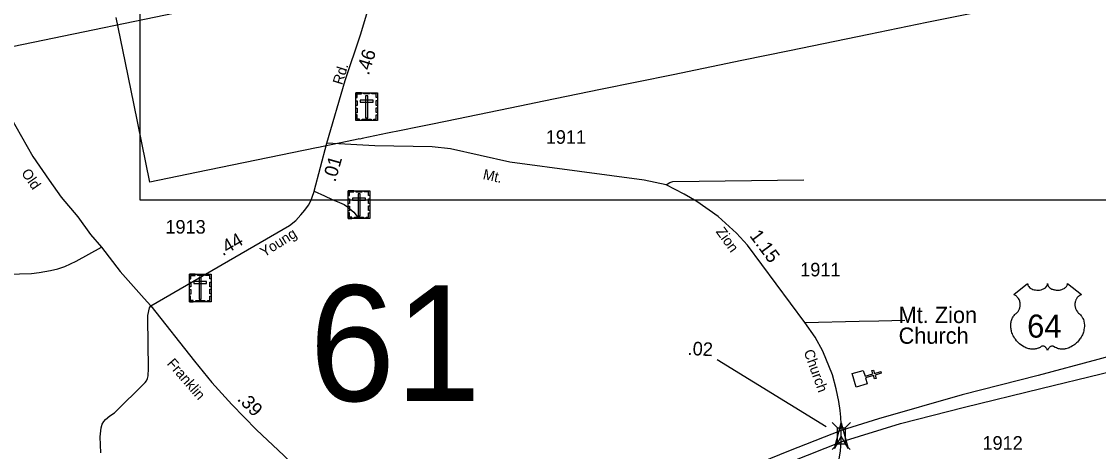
# Model space of a CAD drawing. Extents: x 2220236 to 2384410, y 720751 to 894131.
# Drawn here: x 2276076 to 2286022, y 800133 to 804098 of the extents above; entities that cross this region are included whole.
import ezdxf

# ---------------------------------------------------------------- set-up
doc = ezdxf.new("R2010")
doc.units = 0
doc.layers.add('Default', color=7, linetype='Continuous')

msp = doc.modelspace()

# ---------------------------------------------------------------- linework, layer by layer
at = {"layer": 'Default'}
for p, q in [((2283507.5, 800360.4), (2282500.3, 800977.1)), ((2283564.2, 800400.2), (2283612.7, 800351.1)), ((2283732.4, 800399.2), (2283683.3, 800350.7)), ((2283613.1, 800200), (2283564.1, 800151.5)), ((2283682.1, 800199.6), (2283730.6, 800150.6))]:
    msp.add_line(p, q, dxfattribs=at)
for points in [[(2277171, 809424), (2288659.7, 809424), (2288659.7, 802451.1), (2277171, 802451.1), (2277171, 809424)], [(2273201.7, 803292.5), (2287925.2, 806334.9), (2293833.8, 807542.5)], [(2274868, 805515.3), (2275230.3, 804631.3), (2275439.7, 804146), (2275637.3, 803794.2), (2275720.9, 803656.1), (2275814.4, 803497), (2275940.6, 803274.3), (2276023.8, 803131), (2276181.6, 802852.5), (2276331.6, 802634.4), (2276442, 802478.6), (2276596.3, 802295.9), (2276713.5, 802134.9), (2276814.4, 802015.9), (2276987.4, 801792.3), (2277210, 801545), (2277268.8, 801475.6)], [(2278895.7, 802974.9), (2279063.8, 803555.6), (2279206.1, 803976.1), (2279303.3, 804291.5), (2279329.6, 804461.7), (2279333.1, 804521.6), (2279332.9, 804555.5), (2279327.4, 804607.5)], [(2284943.8, 804191.9), (2284436.5, 804087.9), (2283902.2, 803978.4), (2283168.2, 803827.9), (2282729.2, 803737.9), (2282095.2, 803608), (2281423.5, 803470.4), (2280899.8, 803363), (2280679, 803317.8), (2280096.5, 803198.4), (2279871.5, 803152.2), (2279733.5, 803123.9), (2279581.8, 803092.8), (2279457.2, 803067.3), (2279338.8, 803043), (2279222, 803019.1), (2279199.2, 803014.4), (2279186.2, 803014.8), (2279186, 803011.8), (2279083.5, 802990.8), (2278861, 802945.1), (2278817.5, 802936.2), (2278798.8, 802932.4), (2277691, 802705.3), (2277260.5, 802617.1), (2277111.8, 803343), (2277010.2, 803838.1), (2276949, 804136.2)], [(2284943.8, 804191.9), (2284436.5, 804087.9), (2283902.2, 803978.4), (2283168.2, 803827.9), (2282729.2, 803737.9), (2282095.2, 803608), (2281423.5, 803470.4), (2280899.8, 803363), (2280679, 803317.8), (2280096.5, 803198.4), (2279871.5, 803152.2), (2279733.5, 803123.9), (2279581.8, 803092.8), (2279457.2, 803067.3), (2279338.8, 803043), (2279222, 803019.1), (2279199.2, 803014.4), (2279186.2, 803014.8), (2279186, 803011.8), (2279083.5, 802990.8), (2278861, 802945.1), (2278817.5, 802936.2), (2278798.8, 802932.4), (2277691, 802705.3), (2277260.5, 802617.1), (2277111.8, 803343), (2277010.2, 803838.1), (2276949, 804136.2)], [(2277268.8, 801475.6), (2278550.6, 802217), (2278608.9, 802261.8), (2278654.3, 802314.3), (2278691.8, 802358.5), (2278725.3, 802404.8), (2278748.9, 802445.1), (2278776.1, 802521.3), (2278778.1, 802533.2), (2278895.7, 802974.9)], [(2283646.8, 800324.9), (2283646, 800388.3), (2283642.1, 800449), (2283636.4, 800509.4), (2283622.9, 800594.6), (2283598.3, 800711.2), (2283566.9, 800839), (2283477.3, 801056.5), (2283404.5, 801185.5), (2283311.3, 801322.5), (2282780.8, 802035.2), (2282679.5, 802146.3), (2282509.2, 802301), (2282313.3, 802438.6), (2282196.7, 802507.4), (2282029.6, 802592.6), (2281827.7, 802634), (2281230.6, 802714.7), (2280586.7, 802802.2), (2280037.8, 802922.9), (2279868.3, 802941.2), (2279339.4, 802952.5), (2278895.7, 802974.9)], [(2282029.6, 802592.6), (2282063.3, 802612.7), (2282092.4, 802621.7), (2283302.5, 802639.6)], [(2278778.1, 802533.2), (2278873.3, 802490.5), (2278945, 802456.9), (2279012.2, 802427.7), (2279054.8, 802409.8), (2279087.3, 802390.3), (2279143.8, 802338.7), (2279167.9, 802313.1), (2279184.2, 802289.1)], [(2290605.7, 802486.4), (2290395.4, 802385.5), (2289854.6, 802145.6), (2289107.4, 801866.1), (2288684.8, 801718.8), (2288169, 801564.3), (2287479.1, 801374.8), (2286900.6, 801221.7), (2286017.6, 800979.7), (2285464.7, 800832.9), (2284762.1, 800654.3), (2283991.4, 800433.4), (2283646.8, 800324.9)], [(2283645.7, 800222.8), (2284194.6, 800389.8), (2284784.4, 800540.5), (2285489.2, 800714.6), (2286046.7, 800848.5), (2286923.9, 801067.2), (2287516.9, 801229), (2288256.4, 801450.6), (2288665.9, 801586.2), (2289152.6, 801755.3), (2289869.2, 802040.3), (2290433.4, 802286), (2290669.3, 802396.4)], [(2274435.5, 801337), (2274979, 801354.1), (2275011.1, 801356.5), (2275032.9, 801362.6), (2275052.7, 801370.8), (2275090.6, 801397.2), (2275397.5, 801719.8), (2275415.2, 801736), (2275437.1, 801750.2), (2275459, 801758.5), (2275478.8, 801762.7), (2275540.8, 801769.2), (2275946.6, 801767), (2276168.5, 801775), (2276238.2, 801783.8), (2276342.2, 801800.6), (2276411.9, 801817.4), (2276475.7, 801838.1), (2276581.3, 801886.9), (2276814.4, 802015.9)], [(2276807.2, 800119), (2276803.6, 800266.8), (2276810.8, 800349.8), (2276821.6, 800385.8), (2276836.9, 800410), (2276852.8, 800426.1), (2276890.1, 800461.6), (2276933.4, 800490.4), (2277217.3, 800767.4), (2277229.3, 800783.6), (2277239.1, 800805.6), (2277244.8, 800829.7), (2277248.2, 800897.6), (2277241.8, 801359.4), (2277243.5, 801387.3), (2277259, 801457.6), (2277268.8, 801475.6)], [(2277268.8, 801475.6), (2277673.3, 800966.8), (2277834.6, 800769.5), (2278018.9, 800565.1), (2278245.8, 800333.4), (2278497.9, 800096.8), (2278652.6, 799942.1)], [(2283311.3, 801322.5), (2283813, 801335.1), (2283994.8, 801336.9), (2284232.7, 801345)], [(2283646.8, 800324.9), (2283159.5, 800135.1), (2282826.3, 799998.8), (2282481.9, 799844.5), (2282228.6, 799720.6), (2281976.1, 799583.6), (2281428.9, 799287.1), (2281317.4, 799227.3)], [(2283645.7, 800222.8), (2283647.3, 800294.4), (2283646.8, 800324.9)], [(2281321.5, 799113.9), (2281464.9, 799194.7), (2282012.5, 799496.5), (2282250, 799622.7), (2282523.5, 799760), (2282845.4, 799901.9), (2283187.6, 800039.3), (2283645.7, 800222.8)], [(2283561.3, 799786.2), (2283593.8, 799915.2), (2283609.5, 799966.8), (2283633, 800097.9), (2283638.6, 800139.4), (2283644.2, 800180.9), (2283645.4, 800217.4), (2283645.7, 800222.8)]]:
    msp.add_lwpolyline(points, dxfattribs=at)
for points in [[(2279163.8, 803441.6), (2279362.9, 803441.6), (2279362.9, 803186.9), (2279163.8, 803186.9)], [(2279163.8, 803398.3), (2279175.2, 803398.3), (2279175.2, 803430.5), (2279215.7, 803430.4), (2279215.7, 803441.6), (2279163.8, 803441.6)], [(2279204.6, 803373.5), (2279204.6, 803354.8), (2279322.4, 803354.8), (2279322.4, 803373.5)], [(2279237.9, 803441.6), (2279289.7, 803441.6), (2279289.7, 803430.2), (2279237.9, 803430.2)], [(2279272.8, 803412.3), (2279254.2, 803412.3), (2279254.2, 803209.5), (2279272.8, 803209.5)], [(2279363, 803398.2), (2279351.6, 803398.2), (2279351.6, 803430.4), (2279311.1, 803430.4), (2279311.1, 803441.5), (2279363, 803441.5)], [(2279351.6, 803325.1), (2279351.6, 803368.5), (2279362.9, 803368.5), (2279362.9, 803325.1)], [(2279163.8, 803324.1), (2279163.8, 803367.4), (2279175.2, 803367.4), (2279175.2, 803324.1)], [(2279163.8, 803256.9), (2279163.8, 803300.2), (2279175.2, 803300.2), (2279175.2, 803256.9)], [(2279351.5, 803259.2), (2279351.5, 803302.5), (2279362.9, 803302.5), (2279362.9, 803259.2)], [(2279196.9, 803187), (2279196.9, 803198.5), (2279174.9, 803198.5), (2279174.9, 803238.9), (2279163.8, 803238.9), (2279163.8, 803187)], [(2279221.3, 803198.4), (2279306.1, 803198.4), (2279306.1, 803187), (2279221.3, 803187)], [(2279329.8, 803186.9), (2279329.8, 803198.4), (2279351.8, 803198.4), (2279351.8, 803238.8), (2279362.9, 803238.8), (2279362.9, 803186.9)], [(2279093.2, 802537.2), (2279292.3, 802537.2), (2279292.3, 802282.6), (2279093.2, 802282.6)], [(2279093.2, 802493.9), (2279104.6, 802493.9), (2279104.6, 802526.1), (2279145.1, 802526.1), (2279145.1, 802537.2), (2279093.2, 802537.2)], [(2279167.3, 802537.2), (2279219.1, 802537.2), (2279219.1, 802525.8), (2279167.3, 802525.8)], [(2279202.3, 802507.9), (2279183.6, 802507.9), (2279183.6, 802305.1), (2279202.3, 802305.1)], [(2279292.4, 802493.9), (2279281, 802493.9), (2279281, 802526.1), (2279240.5, 802526), (2279240.5, 802537.2), (2279292.4, 802537.2)], [(2279093.2, 802419.8), (2279093.2, 802463.1), (2279104.6, 802463.1), (2279104.6, 802419.8)], [(2279093.2, 802352.5), (2279093.2, 802395.9), (2279104.6, 802395.9), (2279104.6, 802352.5)], [(2279134, 802469.2), (2279134, 802450.5), (2279251.8, 802450.5), (2279251.8, 802469.2)], [(2279280.9, 802354.9), (2279280.9, 802398.2), (2279292.3, 802398.2), (2279292.3, 802354.9)], [(2279281, 802420.8), (2279281, 802464.1), (2279292.4, 802464.1), (2279292.4, 802420.8)], [(2279126.3, 802282.6), (2279126.3, 802294.1), (2279104.3, 802294.1), (2279104.3, 802334.5), (2279093.2, 802334.5), (2279093.2, 802282.6)], [(2279150.7, 802294.1), (2279235.5, 802294.1), (2279235.5, 802282.7), (2279150.7, 802282.7)], [(2279259.2, 802282.6), (2279259.2, 802294.1), (2279281.2, 802294.1), (2279281.2, 802334.5), (2279292.3, 802334.5), (2279292.3, 802282.6)], [(2277626.9, 801768.3), (2277826, 801768.3), (2277826, 801513.7), (2277626.9, 801513.7)], [(2277626.9, 801725), (2277638.3, 801725), (2277638.3, 801757.2), (2277678.8, 801757.2), (2277678.8, 801768.3), (2277626.9, 801768.3)], [(2277626.9, 801650.8), (2277626.9, 801694.1), (2277638.3, 801694.1), (2277638.3, 801650.8)], [(2277667.7, 801700.2), (2277667.7, 801681.5), (2277785.5, 801681.5), (2277785.5, 801700.2)], [(2277701, 801768.3), (2277752.8, 801768.3), (2277752.8, 801756.9), (2277701, 801756.9)], [(2277735.9, 801739), (2277717.3, 801739), (2277717.3, 801536.2), (2277735.9, 801536.2)], [(2277826.1, 801724.9), (2277814.7, 801724.9), (2277814.7, 801757.1), (2277774.2, 801757.1), (2277774.2, 801768.2), (2277826.1, 801768.2)], [(2277814.7, 801651.8), (2277814.7, 801695.2), (2277826.1, 801695.2), (2277826.1, 801651.8)], [(2285368.3, 801682), (2285368.6, 801676.7), (2285369.9, 801670.4), (2285370.9, 801667.1), (2285373.9, 801660.9), (2285378.7, 801653.5), (2285385.5, 801646.3), (2285393.2, 801640), (2285398.4, 801636.7), (2285407.1, 801632), (2285417.1, 801627.8), (2285428.2, 801624.6), (2285439.5, 801622.3), (2285451.9, 801620.9), (2285464.1, 801620.7), (2285477.3, 801621.7), (2285491.9, 801624.5), (2285498.7, 801626.3), (2285506.2, 801628.8), (2285513.2, 801631.7), (2285520.8, 801635.8), (2285527, 801639.8), (2285531.8, 801643.3), (2285538.6, 801649.8), (2285544.1, 801656.6), (2285546.3, 801660.4), (2285548.3, 801664), (2285551, 801671.8), (2285551.8, 801675.2), (2285552.3, 801682.3), (2285552.8, 801676.3), (2285553.4, 801672.6), (2285554.4, 801669), (2285555.9, 801665.1), (2285558.6, 801659.6), (2285561.7, 801655.1), (2285567.4, 801648.3), (2285571, 801644.9), (2285574.2, 801642.3), (2285583, 801636.3), (2285593.2, 801631.1), (2285598.2, 801628.9), (2285603.3, 801627.1), (2285609.9, 801625.1), (2285616.6, 801623.5), (2285623.3, 801622.4), (2285630.2, 801621.4), (2285637.1, 801620.9), (2285642.8, 801620.7), (2285649.8, 801620.8), (2285656.3, 801621.2), (2285662.9, 801621.9), (2285670.2, 801623.1), (2285676, 801624.4), (2285683.8, 801626.5), (2285690.8, 801629), (2285696.9, 801631.6), (2285704.9, 801635.8), (2285711.3, 801639.9), (2285716.1, 801643.7), (2285721.7, 801648.8), (2285727, 801655), (2285730.1, 801659.5), (2285732.3, 801664.1), (2285734.4, 801669), (2285735.6, 801674.1), (2285736.2, 801678.6), (2285736.3, 801682.4), (2285864.9, 801580), (2285861.9, 801578.8), (2285854.9, 801575.4), (2285849.4, 801572.1), (2285840.5, 801565.9), (2285836.7, 801562.5), (2285832.9, 801558.9), (2285829.4, 801555.1), (2285826.4, 801551.6), (2285822.6, 801546.4), (2285819.3, 801541.2), (2285816, 801535.5), (2285813.6, 801530.6), (2285809.7, 801520.2), (2285807.8, 801513.7), (2285806.6, 801508.2), (2285805.1, 801496.7), (2285804.7, 801491.2), (2285804.7, 801485.8), (2285805, 801480.1), (2285805.5, 801474.7), (2285806.5, 801469), (2285807.4, 801463.9), (2285809, 801457.8), (2285811.3, 801450.6), (2285814.1, 801443.7), (2285820, 801432.6), (2285827.5, 801421.2), (2285832.9, 801414.8), (2285838.2, 801409.3), (2285846.2, 801402.6), (2285850.5, 801398.8), (2285855.4, 801393.9), (2285863.5, 801384.5), (2285866.7, 801380.1), (2285870, 801375.2), (2285873.1, 801370.1), (2285876.1, 801364.6), (2285878.5, 801359.8), (2285883.1, 801348.8), (2285886.4, 801338.1), (2285887.9, 801332.5), (2285890.3, 801319.9), (2285891.2, 801313.6), (2285892.2, 801301.3), (2285892.2, 801286.4), (2285891.1, 801272.3), (2285888.4, 801255.8), (2285886.2, 801245.9), (2285882.8, 801234.5), (2285879.6, 801224.5), (2285873.7, 801209.8), (2285868.5, 801199.2), (2285861.7, 801186.7), (2285857.1, 801179.2), (2285851.7, 801171.2), (2285844.9, 801161.9), (2285837, 801152), (2285827.5, 801141.6), (2285819.9, 801133.9), (2285809.8, 801125), (2285803.8, 801120), (2285795.1, 801113.4), (2285783.3, 801105.5), (2285771.6, 801098.8), (2285761.6, 801093.7), (2285752.8, 801089.9), (2285741.4, 801085.5), (2285722.4, 801080.3), (2285715.5, 801078.8), (2285707.3, 801077.6), (2285699.7, 801076.9), (2285692.2, 801076.4), (2285682.2, 801076.4), (2285672.2, 801077.2), (2285662.8, 801078.5), (2285653, 801080.6), (2285642.8, 801083.6), (2285633.5, 801087.3), (2285624, 801091.9), (2285608.1, 801101.9), (2285603.5, 801104.4), (2285601, 801105.1), (2285594.8, 801105.4), (2285589, 801104.1), (2285583.1, 801101.8), (2285579.5, 801099.9), (2285574.8, 801096.8), (2285571.1, 801093.9), (2285566.7, 801089.7), (2285563.7, 801086.2), (2285561.4, 801083.5), (2285556.9, 801076.4), (2285555.3, 801073.1), (2285553.6, 801068.7), (2285552.2, 801062.4), (2285550.1, 801070.4), (2285547.8, 801075.7), (2285545.1, 801080.3), (2285542.2, 801084.3), (2285537.7, 801089.5), (2285533.7, 801093.4), (2285528.8, 801097.3), (2285523.7, 801100.4), (2285519.5, 801102.5), (2285515.7, 801104), (2285511.1, 801105.1), (2285507.3, 801105.4), (2285504.2, 801105.4), (2285499.9, 801104.4), (2285494.1, 801100.2), (2285488.6, 801096.4), (2285482.6, 801092.7), (2285475.5, 801088.9), (2285470.2, 801086.4), (2285464, 801084), (2285456.7, 801081.6), (2285448.8, 801079.5), (2285440.7, 801077.9), (2285433.5, 801076.8), (2285425.9, 801076.1), (2285418.9, 801075.9), (2285411.7, 801076), (2285405, 801076.5), (2285397.2, 801077.2), (2285387.4, 801078.6), (2285379.4, 801080.4), (2285370.9, 801082.7), (2285362.1, 801085.5), (2285352.8, 801089), (2285341.1, 801094.1), (2285333, 801098.3), (2285320.1, 801105.7), (2285305.1, 801116.1), (2285293.8, 801125.3), (2285285.4, 801132.8), (2285273.2, 801145.3), (2285266, 801153.4), (2285254.8, 801168), (2285247.5, 801178.5), (2285242.9, 801186.3), (2285236, 801198.7), (2285232.3, 801206.6), (2285227.4, 801218), (2285223.6, 801228.4), (2285220.4, 801238.3), (2285218.7, 801244.6), (2285216.2, 801255.6), (2285214.8, 801263.4), (2285213.3, 801274.1), (2285212.5, 801285.4), (2285212.4, 801295.9), (2285212.6, 801304.5), (2285213.6, 801314.6), (2285215.3, 801325.3), (2285217.4, 801334.5), (2285219.3, 801341.1), (2285222, 801349.2), (2285225.6, 801358.1), (2285229.8, 801366.6), (2285233.9, 801373.7), (2285239, 801381.3), (2285244, 801387.7), (2285250.6, 801394.9), (2285257.4, 801401.4), (2285263.7, 801406.5), (2285271.1, 801413.8), (2285275, 801418.2), (2285279.7, 801424.4), (2285283.4, 801430.1), (2285286.4, 801435.1), (2285290.3, 801442.7), (2285292.6, 801448.3), (2285295.6, 801457), (2285297.1, 801463), (2285298.6, 801470.9), (2285299.6, 801478.2), (2285299.9, 801487.4), (2285299.7, 801495), (2285298.7, 801503.9), (2285297.1, 801512.4), (2285295, 801519.9), (2285291.9, 801528.4), (2285288.9, 801534.6), (2285284, 801543), (2285278.5, 801550.9), (2285272.9, 801557.3), (2285267.2, 801563), (2285261.7, 801567.2), (2285256.5, 801570.9), (2285250, 801574.9), (2285243.7, 801578), (2285239.7, 801579.6)], [(2277626.9, 801583.6), (2277626.9, 801626.9), (2277638.3, 801626.9), (2277638.3, 801583.6)], [(2277814.6, 801585.9), (2277814.6, 801629.2), (2277826, 801629.2), (2277826, 801585.9)], [(2277660, 801513.7), (2277660, 801525.2), (2277638, 801525.2), (2277638, 801565.6), (2277626.9, 801565.6), (2277626.9, 801513.7)], [(2277684.4, 801525.1), (2277769.2, 801525.1), (2277769.2, 801513.7), (2277684.4, 801513.7)], [(2277792.9, 801513.7), (2277792.9, 801525.1), (2277814.9, 801525.1), (2277814.9, 801565.6), (2277826, 801565.6), (2277826, 801513.7)], [(2283850.1, 800880.6), (2283866.2, 800826), (2283939.3, 800847.4), (2283930.3, 800878.1), (2283945.6, 800882.6), (2283954.6, 800851.9), (2284012.3, 800868.8), (2284016.9, 800853.5), (2283959.1, 800836.5), (2283968.2, 800805.8), (2283952.8, 800801.3), (2283943.8, 800832), (2283870.8, 800810.6), (2283886.9, 800755.3), (2283784.7, 800725.3), (2283748, 800850.6)], [(2283583.1, 800161.3), (2283647.5, 800396.5), (2283709.3, 800160.6), (2283646.8, 800274.5)], [(2283683.3, 800350.7), (2283682.5, 800199.6), (2283611.9, 800200), (2283612.7, 800351.1)]]:
    msp.add_lwpolyline(points, close=True, dxfattribs=at)

# ---------------------------------------------------------------- texts
for s, height, rotation, p in [('.46', 125, 72.70848, (2279282.1, 803597.1)), ('Rd.', 95, 72.70848, (2279037.6, 803508.1)), ('.01', 125, 73.87395, (2278973.9, 802612.5)), ('Old', 95, 304.8693, (2276069.5, 802700.3)), ('Mt.', 95, 347.28795, (2280331.7, 802646.7)), ('Young', 95, 32.21004, (2278316.9, 801921.8)), ('Zion', 95, 305.64182, (2282484.8, 802160.1)), ('.44', 125, 30.04485, (2277933.9, 801932.4)), ('1.15', 125, 306.66217, (2282794.7, 802121.3)), ('.02', 125, 356.97903, (2282225.6, 801023.4)), ('Franklin', 95, 311.04179, (2277413.8, 800940.4)), ('Church', 95, 289.75737, (2283298.5, 801054)), ('.39', 125, 314.39595, (2278062.2, 800610.2))]:
    msp.add_text(s, height=height, rotation=rotation, dxfattribs=at).set_placement(p)
for s, height, p in [('1911', 125, (2280917.9, 802970.6)), ('1913', 125, (2277405.1, 802141.9)), ('1911', 125, (2283267.8, 801747.6)), ('61', 1066.27, (2278733.7, 800598.2)), ('Mt. Zion ', 150, (2284176.8, 801317)), ('64', 212.5, (2285364, 801182.7)), ('Church', 150, (2284176.8, 801126)), ('1912', 125, (2284951.2, 800148.9))]:
    msp.add_text(s, height=height, dxfattribs=at).set_placement(p)

doc.saveas('drawing.dxf')
